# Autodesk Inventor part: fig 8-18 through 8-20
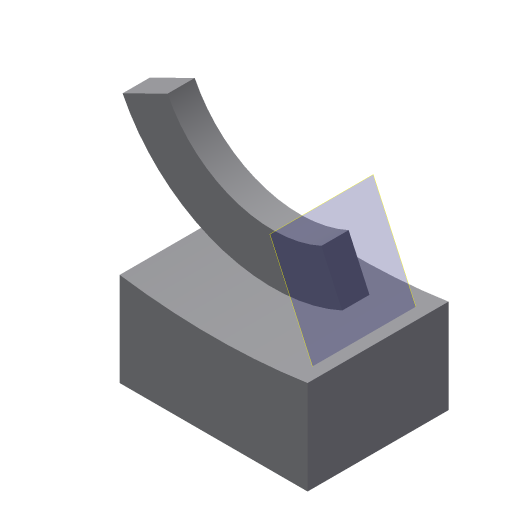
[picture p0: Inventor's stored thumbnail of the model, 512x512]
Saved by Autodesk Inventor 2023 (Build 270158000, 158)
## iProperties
Created: 2010-03
Part Number: fig 8-18 through 8-20
Document SubType Name: Modeling
Designer: CADSoft
Density: 1 g/cm^3
Material: Generic
Appearance: Default
Author: CADSoft
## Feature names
1. Extrusion1
2. Sweep3
## Parameters: d10 = 0, d13 = 0, d14 = 0
